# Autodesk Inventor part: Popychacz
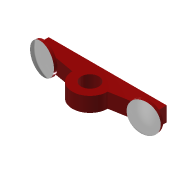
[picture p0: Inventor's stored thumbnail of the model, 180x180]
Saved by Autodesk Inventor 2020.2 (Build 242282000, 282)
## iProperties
Created: 2005-10
Part Number: Popychacz
Document SubType Name: Modeling
Designer: F.Stasiak
Density: 1 g/cm^3
Material: Ogólny
Appearance: Czerwona
Manager: www.cadconsulting.pl
Company: Fabian Stasiak CAD Consulting
Author: F.Stasiak
Subject: Zbiór ćwiczeń. Autodesk Inventor 2020. Kurs podstawowy
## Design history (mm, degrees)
sketch "Szkic1"
  geometry: L1 (6, 0)-(20, 2.469); L2 (20, 2.469)-(20, 6); L3 (20, 6)-(0, 6); L4 (0, 0)-(0, 6); L5 (-20, 6)-(0, 6); L6 (-20, 2.469)-(-20, 6); L7 (-6, 0)-(-20, 2.469); L8 (-6, 0)-(6, 0); C1 r 3 at (0, 0); A1 r 6 centre (0, 0) between (-6, 0) and (6, 0); 2 further points
  constraints: 16 end point, 3 coincident, 3 perpendicular, 3 symmetric about line, 2 centre point, 2 point on circle, 1 midpoint, 1 vertical
  dimensions: "d0" = 6 diameter of C1; "d1" = 12 diameter of A1; "d2" = 40 distance between parallel lines of L2 L6; "d3" = 6 distance of L4.start L3.end; "d4" = 160 deg angle of L7 L1
extrude "Wyciągnięcie proste1" new body sketch "Szkic1" stored distance "d5" = 5; taper "d6" = 0 deg
sketch "Szkic2"
  geometry: L1 (20, 2.469)-(6, 0) reference; L2 (17.046, 1.948)-(21.97, 2.816); L3 (21.97, 2.816)-(22.143, 1.831); L4 (17.046, 1.948)-(17.393, -0.022); L5 (17.393, -0.022)-(16.408, -0.196); A1 r 13 centre (15.135, 12.781) between (17.393, -0.022) and (22.143, 1.831)
  constraints: 8 end point, 2 perpendicular, 2 point on circle, 2 point on line, 1 centre point, 1 parallel, 1 tangent
  dimensions: "d8" = 1 distance of L2.end L3.end; "d11" = 2 distance of L2.start L4.end; "d13" = 5 distance of L2.start L2.end; "d15" = 2 distance from line of L1.start L3; "d16" = 6 distance from line of L5.end L3
revolve "Obrót1" sketch "Szkic2" stored, may be unused: angle "d14" = 90 deg
mirror "Lustro1"
node "Bryła1"
node "Korpusy bryłowe"
node "Korpusy powierzchniowe"
